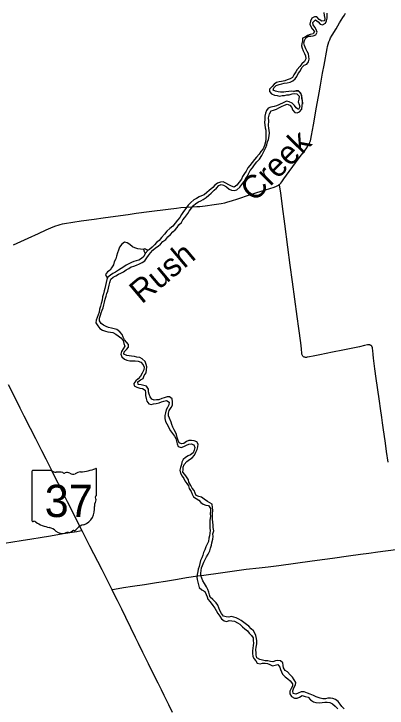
# Model space of a CAD drawing. Extents: x 0 to 680, y 0 to 440.
# Drawn here: x 136.6 to 190.2, y 233.7 to 333.5 of the extents above; entities that cross this region are included whole.
import ezdxf

# ---------------------------------------------------------------- set-up
doc = ezdxf.new("R2010")
doc.units = 0
for name, color, linetype in [('GM_X_County_Road', 7, 'Continuous'), ('GM_X_Minor_Lake', 7, 'Continuous'), ('GM_X_Minor_River', 7, 'Continuous'), ('GM_X_Minor_River_Text', 7, 'Continuous'), ('GM_X_State_Location', 7, 'Continuous'), ('GM_X_State_Route', 7, 'Continuous'), ('GM_X_State_Shield', 7, 'Continuous'), ('GM_X_Township_Road', 7, 'Continuous')]:
    doc.layers.add(name, color=color, linetype=linetype)

msp = doc.modelspace()

# ---------------------------------------------------------------- linework, layer by layer
at = {"layer": 'GM_X_County_Road'}
for points in [[(174.704, 308.957), (174.764, 309.006), (174.846, 309.082), (174.921, 309.163), (175.061, 309.334), (175.381, 309.78), (176.147, 310.846), (177.574, 312.783), (178.552, 314.1), (178.804, 314.46), (178.919, 314.649), (179.021, 314.845), (179.107, 315.049), (179.177, 315.258), (179.231, 315.472), (179.341, 316.009), (179.613, 317.517), (180.069, 320.101), (180.428, 322.147), (180.626, 323.222), (180.929, 324.946), (181.134, 326.131), (181.556, 328.499), (181.624, 328.818), (181.71, 329.132), (181.815, 329.441), (181.939, 329.742), (182.078, 330.038), (182.285, 330.421), (182.855, 331.353), (183.359, 332.2), (183.807, 332.95), (184.046, 333.314), (184.219, 333.577)], [(136.557, 300.312), (138.649, 301.261), (140.143, 301.938), (141.24, 302.432), (142.24, 302.872), (142.644, 303.036), (142.953, 303.143), (143.266, 303.235), (143.583, 303.31), (143.905, 303.37), (146.284, 303.724), (148.124, 303.989), (149.422, 304.184), (150.505, 304.337), (152.998, 304.667), (154.189, 304.837), (156.034, 305.068), (158.745, 305.425), (159.938, 305.58), (160.589, 305.65), (161.352, 305.702), (162.881, 305.783), (163.318, 305.819), (164.079, 305.916), (165.379, 306.098), (166.352, 306.25), (166.891, 306.353), (167.318, 306.455), (167.844, 306.608), (168.78, 306.914), (170.443, 307.461), (172.106, 308.004), (173.984, 308.598), (174.295, 308.713), (174.493, 308.812), (174.588, 308.871), (174.678, 308.935), (174.704, 308.957)], [(150.678, 250.749), (151.039, 250.812), (152.333, 251.037), (153.631, 251.239), (155.36, 251.511), (157.09, 251.783), (158.387, 251.987), (160.115, 252.266), (161.412, 252.474), (163.035, 252.722), (163.902, 252.845), (166.285, 253.187), (167.261, 253.318), (169.973, 253.682), (171.822, 253.893), (173.126, 254.04), (174.645, 254.241), (179.416, 254.892), (181.26, 255.135), (182.344, 255.281), (184.621, 255.598), (186.356, 255.83), (187.548, 256), (188.85, 256.173), (191.452, 256.527)]]:
    msp.add_lwpolyline(points, dxfattribs=at)
at = {"layer": 'GM_X_Minor_Lake'}
for points in [[(155.876, 299.531), (155.663, 299.562), (155.491, 299.671), (155.332, 299.714), (155.264, 299.635), (155.235, 299.515), (155.34, 299.38), (155.402, 299.138), (155.468, 299.07)], [(155.468, 299.07), (155.876, 299.531)]]:
    msp.add_lwpolyline(points, dxfattribs=at)
at = {"layer": 'GM_X_Minor_River'}
for points in [[(181.104, 333.695), (181.137, 333.253), (181.237, 332.837), (181.177, 332.464), (180.803, 332.417), (180.433, 332.677), (180.092, 333.043), (179.746, 333.076), (179.382, 332.854), (179.175, 332.444), (179.101, 332.004), (179.242, 331.667), (179.45, 331.316), (179.738, 330.964), (179.558, 330.606), (179.13, 330.519), (178.754, 330.392), (178.416, 330.143), (178.053, 329.989), (178.021, 329.615), (177.961, 329.242), (177.915, 328.882), (177.976, 328.547), (178.157, 328.156), (178.325, 327.792), (178.479, 327.442), (178.499, 327.014), (178.319, 326.629), (177.926, 326.302), (177.653, 325.932), (177.259, 325.497), (177.08, 325.153), (176.819, 324.703), (176.613, 324.358), (176.249, 324.151), (175.846, 323.983), (175.484, 323.856), (175.041, 323.756), (174.68, 323.695), (174.318, 323.621), (173.968, 323.399), (173.682, 323.057), (173.302, 322.675), (173.309, 322.314), (173.611, 321.975), (174.008, 321.808), (174.394, 321.735), (174.754, 321.662), (175.115, 321.736), (175.462, 321.744), (175.798, 321.832), (176.132, 321.867)], [(176.754, 322.351), (176.407, 322.384), (176.072, 322.309), (175.671, 322.275), (175.337, 322.241), (174.897, 322.248), (174.537, 322.267), (174.178, 322.367), (173.833, 322.506), (173.906, 322.866), (174.271, 323.194), (174.674, 323.334), (175.063, 323.435), (175.398, 323.51), (175.852, 323.556), (176.255, 323.683), (176.645, 323.863), (176.997, 324.138), (177.203, 324.496), (177.423, 324.893), (177.682, 325.25), (177.931, 325.794), (178.297, 326.135), (178.673, 326.236), (178.919, 326.593), (179.006, 326.993), (178.959, 327.381), (178.885, 327.756), (178.703, 328.094), (178.536, 328.457), (178.343, 328.915), (178.229, 329.304), (178.315, 329.651), (178.534, 330.021), (178.872, 330.283), (179.219, 330.277), (179.554, 330.312), (179.93, 330.493), (180.15, 330.837), (179.996, 331.227), (179.828, 331.564), (179.58, 331.902), (179.518, 332.237), (179.899, 332.632), (180.268, 332.359), (180.556, 331.993), (180.928, 331.893), (181.319, 332.128), (181.471, 332.486), (181.558, 332.886), (181.569, 333.594)], [(150.548, 295.369), (150.887, 295.671), (151.25, 295.852), (151.628, 296.06), (151.977, 296.228), (152.328, 296.422), (152.746, 296.683), (153.11, 296.904), (153.474, 297.152), (153.836, 297.24), (154.239, 297.393), (154.629, 297.547), (155.02, 297.781), (155.424, 298.015), (155.698, 298.425), (155.931, 298.782), (156.23, 299.138), (156.544, 299.547), (156.949, 299.861), (157.314, 300.096), (157.653, 300.411), (158.019, 300.752), (158.424, 301.08), (158.724, 301.422), (159.104, 301.79), (159.416, 302.146), (159.769, 302.461), (160.041, 302.804), (160.301, 303.187), (160.68, 303.502), (160.873, 303.886), (161.159, 304.229), (161.582, 304.797), (161.762, 305.155), (162.089, 305.577), (162.376, 305.96), (162.754, 306.234), (163.091, 306.456), (163.427, 306.598), (163.778, 306.819), (164.197, 307.106), (164.589, 307.42), (164.927, 307.709), (165.349, 308.156), (165.714, 308.445), (166.04, 308.8), (166.376, 308.942), (166.722, 308.869), (167.118, 308.622), (167.5, 308.281), (167.872, 308.168), (168.257, 308.082), (168.62, 308.21), (169.053, 308.563), (169.339, 308.946), (169.667, 309.409), (169.901, 309.819), (170.16, 310.162), (170.286, 310.508), (170.534, 310.958), (170.861, 311.381), (171.148, 311.804), (171.502, 312.199), (171.869, 312.607), (172.185, 313.136), (172.378, 313.521), (172.764, 314.263), (172.918, 314.688), (173.031, 315.074), (173.17, 315.446), (173.272, 315.952), (173.293, 316.393), (173.258, 316.741), (173.197, 317.076), (173.176, 317.438), (173.214, 318.132), (173.181, 318.533), (173.284, 319.12), (173.557, 319.53), (173.893, 319.631), (174.296, 319.798), (174.646, 319.98), (175.023, 320.161), (175.467, 320.367), (175.843, 320.495), (176.241, 320.368), (176.502, 320.029), (176.59, 319.694), (176.931, 319.301), (177.264, 319.282), (177.627, 319.423), (177.927, 319.792), (178.015, 320.299), (178.034, 320.633), (178.026, 320.967), (177.965, 321.342), (177.945, 321.717), (177.804, 322.067), (177.476, 322.406), (177.129, 322.438), (176.754, 322.351)], [(176.754, 322.351), (177.102, 322.412), (177.449, 322.393), (177.803, 322), (177.877, 321.651), (177.938, 321.302), (177.973, 320.968), (178.047, 320.632), (178.058, 320.485)], [(176.132, 321.867), (176.561, 322.007), (176.909, 322.028), (177.242, 322.009), (177.544, 321.67), (177.51, 321.229), (177.436, 320.829), (177.564, 320.44), (177.665, 320.104), (177.472, 319.72), (177.129, 319.966), (176.908, 320.33), (176.553, 320.67), (176.128, 320.838), (175.743, 320.924), (175.38, 320.756), (174.653, 320.394), (174.303, 320.253), (173.968, 320.151), (173.513, 320.078), (173.11, 319.938), (172.878, 319.594), (172.711, 319.223), (172.611, 318.783), (172.616, 318.275), (172.584, 317.942), (172.69, 317.098), (172.765, 316.763), (172.797, 316.308), (172.777, 315.894), (172.758, 315.546), (172.71, 315.079), (172.595, 314.587), (172.374, 314.109), (172.047, 313.7), (171.814, 313.343), (171.42, 312.909), (171.147, 312.552), (170.82, 312.116), (170.479, 311.708), (170.193, 311.338), (169.945, 310.901), (169.726, 310.544), (169.412, 310.135), (169.286, 309.736), (168.945, 309.314), (168.604, 308.865), (168.238, 308.563), (167.867, 308.703), (167.484, 308.937), (167.06, 309.171), (166.663, 309.351), (166.275, 309.304), (165.832, 309.151), (165.481, 308.889), (165.181, 308.533), (164.667, 308.114), (164.288, 307.8), (163.936, 307.498), (163.546, 307.344), (163.21, 307.176), (162.806, 306.955), (162.429, 306.761), (162.009, 306.367), (161.615, 305.972), (161.274, 305.497), (160.973, 305.074), (160.672, 304.638), (160.438, 304.228), (160.085, 303.819), (159.771, 303.41), (159.43, 303.001), (159.024, 302.634), (158.577, 302.24), (158.223, 301.818), (157.815, 301.344), (157.447, 300.909), (157.109, 300.62), (156.796, 300.278), (156.457, 299.963), (156.064, 299.622), (155.876, 299.531)], [(155.257, 299.606), (154.771, 299.683), (154.385, 299.743), (153.999, 299.843), (153.654, 299.996), (153.246, 300.323), (152.876, 300.57), (152.478, 300.67), (152.126, 300.395), (151.798, 299.946), (151.631, 299.534), (151.505, 299.136), (151.35, 298.644), (151.237, 298.285), (151.017, 297.874), (150.916, 297.408), (150.642, 296.985), (150.436, 296.641), (150.045, 296.42), (149.772, 296.05), (149.98, 295.593)], [(155.468, 299.07), (155.26, 298.619), (154.922, 298.318), (154.571, 298.096), (154.182, 297.996), (153.847, 297.908), (153.498, 297.78), (153.121, 297.559), (152.757, 297.351), (152.379, 297.117), (152.028, 296.882), (151.624, 296.648), (151.205, 296.374), (150.829, 296.193), (150.465, 295.959), (150.099, 295.657), (149.946, 295.299), (149.873, 294.873), (149.772, 294.447), (149.672, 294.034), (149.559, 293.688), (149.459, 293.236), (149.331, 292.81), (149.27, 292.343), (149.169, 291.877), (149.042, 291.465), (148.929, 291.039), (148.855, 290.626), (148.589, 289.869), (148.435, 289.47), (148.39, 289.11), (148.649, 288.652), (148.936, 288.259), (149.36, 288.039), (149.758, 287.912), (150.103, 287.813), (150.476, 287.753), (150.836, 287.694), (151.246, 287.46), (151.589, 287.227), (151.971, 286.913), (152.285, 286.547), (152.412, 286.131), (152.526, 285.755), (152.319, 285.357), (152.086, 284.987), (151.959, 284.588), (152.127, 284.211), (152.508, 283.844), (152.852, 283.705), (153.265, 283.604), (153.638, 283.612), (154.039, 283.645), (154.452, 283.598), (154.837, 283.431), (155.151, 283.065), (155.306, 282.715), (155.246, 282.329), (155.051, 281.864), (154.79, 281.428), (154.437, 281.059), (154.098, 280.731), (153.825, 280.361), (153.886, 280.026), (154.257, 279.86), (154.709, 279.719), (155.095, 279.632), (155.438, 279.412), (155.499, 279.037), (155.505, 278.623), (155.605, 278.194), (155.692, 277.831), (155.966, 277.453), (156.325, 277.353), (156.661, 277.468), (157.048, 277.488), (157.477, 277.575), (157.813, 277.716), (158.162, 277.831), (158.537, 277.918), (158.921, 277.711), (158.874, 277.311), (158.654, 276.941), (158.462, 276.596), (158.374, 276.157), (158.301, 275.757), (158.294, 275.33), (158.381, 274.927), (158.589, 274.59), (158.744, 274.253), (158.925, 273.903), (159.093, 273.566), (159.38, 273.2), (159.654, 272.822), (159.849, 272.471), (159.976, 272.095), (160.063, 271.719), (160.203, 271.303), (160.629, 271.189), (161.018, 271.303), (161.381, 271.51)], [(160.85, 267.63), (160.896, 268.004), (160.915, 268.338), (161.042, 268.71), (161.463, 269.17), (161.841, 269.445), (162.219, 269.679), (162.559, 270.061), (162.739, 270.486), (162.906, 270.884), (163.033, 271.269), (163.066, 271.643), (162.871, 271.994), (162.486, 272.12), (162.087, 272.18), (161.74, 272.186), (161.377, 272.045), (161.025, 271.77), (160.677, 271.709), (160.332, 271.822), (160.178, 272.185), (160.065, 272.614), (159.951, 273.031), (159.797, 273.367), (159.629, 273.704), (159.449, 274.108), (159.295, 274.498), (159.194, 274.834), (158.949, 275.372), (158.795, 275.736), (158.814, 276.096), (158.9, 276.469), (159.174, 276.905), (159.394, 277.263), (159.389, 277.757), (159.328, 278.146), (158.96, 278.472), (158.599, 278.452), (158.169, 278.298), (157.834, 278.197), (157.444, 278.03), (157.097, 278.022), (156.763, 277.974), (156.418, 278.127), (156.183, 278.465), (156.016, 278.855), (155.928, 279.191), (155.921, 279.552), (155.634, 279.971), (155.262, 280.07), (154.863, 280.184), (154.464, 280.23), (154.416, 280.592), (154.768, 280.88), (155.186, 281.1), (155.312, 281.513), (155.586, 281.882), (155.673, 282.322), (155.72, 282.749), (155.619, 283.098), (155.452, 283.515), (155.045, 283.896), (154.701, 284.102), (154.288, 284.135), (153.929, 284.235), (153.516, 284.282), (153.156, 284.341), (152.811, 284.414), (152.399, 284.567), (152.432, 284.928), (152.771, 285.27), (153.071, 285.612), (153.063, 285.973), (152.802, 286.311), (152.514, 286.664), (152.307, 287.041), (152.139, 287.418), (151.825, 287.798), (151.417, 288.112), (151.005, 288.225), (150.619, 288.325), (150.22, 288.412), (149.849, 288.565), (149.492, 288.758), (149.135, 289.005), (148.901, 289.396), (148.908, 289.77), (149.048, 290.169), (149.147, 290.514), (149.273, 290.9), (149.439, 291.245), (149.539, 291.657), (149.613, 292.044), (149.727, 292.483), (149.88, 292.908), (149.94, 293.308), (150.093, 293.653), (150.193, 294.092), (150.307, 294.491), (150.407, 294.89), (150.548, 295.369)], [(161.381, 271.51), (161.731, 271.665), (162.078, 271.686), (162.437, 271.546), (162.577, 271.183), (162.477, 270.784), (162.364, 270.412), (161.972, 270.097), (161.609, 269.956), (161.246, 269.749), (160.907, 269.434), (160.714, 269.076), (160.668, 268.716), (160.514, 268.304), (160.428, 267.931), (160.541, 267.502), (160.747, 267.044), (160.995, 266.706), (161.163, 266.369), (161.464, 266.003), (161.659, 265.653), (161.786, 265.29), (162.059, 264.844), (162.213, 264.454), (162.42, 264.077), (162.79, 263.857), (163.186, 263.596), (163.461, 263.258), (163.805, 263.052), (164.149, 262.899), (164.535, 262.839), (164.835, 262.407), (164.816, 262.059), (164.77, 261.659), (164.844, 261.284), (164.754, 260.684), (164.761, 260.323), (164.755, 259.976), (164.762, 259.602), (164.783, 259.24), (164.737, 258.854), (164.69, 258.48), (164.618, 258.134), (164.557, 257.667), (164.364, 257.283), (164.171, 256.912), (164.016, 256.46), (163.85, 256.102), (163.737, 255.69), (163.584, 255.332), (163.417, 254.933), (163.317, 254.521), (163.203, 254.068), (163.077, 253.71), (163.03, 253.336), (162.904, 252.937), (162.884, 252.564), (162.918, 252.189), (163.005, 251.813), (163.106, 251.464), (163.233, 251.061), (163.601, 250.708), (164.011, 250.474), (164.191, 250.07), (164.346, 249.72), (164.473, 249.384), (164.787, 248.978), (165.166, 248.477), (165.454, 248.112), (165.661, 247.747), (165.881, 247.329), (166.155, 246.924), (166.429, 246.545), (166.811, 246.258), (167.184, 246.185), (167.519, 246.3), (167.88, 246.281), (168.292, 246.221), (168.689, 245.974), (169.033, 245.781), (169.427, 245.427), (169.783, 245.127), (170.125, 244.827), (170.4, 244.489), (170.741, 244.162), (170.976, 243.825), (170.969, 243.424), (171.003, 243.062), (170.971, 242.702), (170.925, 242.342), (170.852, 241.969), (170.886, 241.581), (170.933, 241.193), (171.06, 240.843), (171.322, 240.505), (171.556, 240.167), (171.942, 240.08), (172.277, 240.168), (172.664, 240.175), (173.011, 240.143), (173.355, 239.99)], [(177.063, 235.733), (176.718, 235.846), (176.657, 236.221), (176.811, 236.646), (177.032, 237.07), (177.064, 237.417), (176.857, 237.808), (176.623, 238.186), (176.255, 238.526), (175.887, 238.92), (175.531, 239.139), (175.297, 239.531), (175.276, 239.865), (175.228, 240.213), (174.872, 240.5), (174.487, 240.586), (174.152, 240.525), (173.789, 240.397), (173.443, 240.416), (173.084, 240.529), (172.67, 240.523), (172.311, 240.609), (171.913, 240.722), (171.503, 240.97), (171.402, 241.332), (171.368, 241.68), (171.361, 242.081), (171.408, 242.494), (171.495, 242.947), (171.476, 243.389), (171.455, 243.736), (171.355, 244.166), (171.214, 244.502), (171.006, 244.84), (170.65, 245.126), (170.323, 245.492), (169.98, 245.752), (169.597, 246.012), (169.242, 246.312), (168.898, 246.531), (168.541, 246.711), (168.195, 246.81), (167.809, 246.883), (167.461, 246.809), (167.075, 246.842), (166.716, 246.955), (166.415, 247.334), (166.182, 247.765), (166.055, 248.142), (165.874, 248.519), (165.64, 248.87), (165.193, 249.332), (164.812, 249.645), (164.684, 249.995), (164.584, 250.398), (164.456, 250.774), (164.249, 251.165), (163.963, 251.61), (163.742, 252.002), (163.589, 252.418), (163.462, 252.795), (163.454, 253.129), (163.487, 253.502), (163.547, 253.876), (163.672, 254.221), (163.88, 254.685), (164.074, 255.083), (164.24, 255.441), (164.5, 255.864), (164.735, 256.328), (164.822, 256.728), (165.002, 257.125), (165.048, 257.486), (165.15, 258.018), (165.196, 258.365), (165.149, 258.767), (165.303, 259.218), (165.204, 259.674), (165.196, 260.022), (165.15, 260.437), (165.144, 260.878), (165.111, 261.306), (165.144, 261.667), (165.177, 262.107), (165.105, 262.576), (165.086, 263.017), (164.742, 263.237), (164.398, 263.429), (163.949, 263.731), (163.568, 264.058), (163.155, 264.118), (162.757, 264.272), (162.629, 264.608), (162.475, 264.984), (162.214, 265.336), (162.007, 265.727), (161.734, 266.199), (161.673, 266.548), (161.373, 266.954), (161.138, 267.292), (160.85, 267.63)], [(173.355, 239.99), (173.739, 239.783), (174.115, 239.884), (174.504, 239.998), (174.765, 239.633), (174.879, 239.284), (175.034, 238.947), (175.188, 238.584), (175.543, 238.244), (175.938, 237.917), (176.28, 237.644), (176.607, 237.237), (176.601, 236.877), (176.409, 236.532), (176.242, 236.161), (176.236, 235.8), (176.456, 235.383), (176.88, 235.175), (177.267, 235.169), (177.603, 235.323), (178.007, 235.531), (178.406, 235.404), (178.831, 235.277), (179.186, 234.937), (179.608, 234.649), (179.953, 234.536), (180.473, 234.474), (180.874, 234.521), (181.249, 234.582), (181.596, 234.576), (181.969, 234.53), (182.326, 234.324), (182.721, 233.983), (183.102, 233.629)], [(184.009, 233.615), (183.695, 233.954), (183.433, 234.292), (183.159, 234.657), (182.777, 234.958), (182.406, 235.111), (182.059, 235.157), (181.685, 235.136), (181.35, 235.061), (180.95, 235.081), (180.551, 235.141), (179.98, 235.324), (179.609, 235.531), (179.158, 235.712), (178.761, 235.892), (178.27, 236.061), (177.856, 236.054), (177.399, 235.888), (177.063, 235.733)]]:
    msp.add_lwpolyline(points, dxfattribs=at)
at = {"layer": 'GM_X_State_Route'}
msp.add_lwpolyline([(135.807, 280.204), (136.75, 278.351), (137.481, 276.882), (138.072, 275.71), (138.966, 273.956), (139.7, 272.488), (140.589, 270.731), (141.183, 269.561), (142.07, 267.803), (142.565, 266.827), (143.353, 265.265), (143.898, 264.192), (144.287, 263.409), (145.021, 261.941), (146.199, 259.594), (146.379, 259.238), (147.483, 257.056), (148.632, 254.818), (149.219, 253.644), (149.717, 252.67), (150.678, 250.749), (150.891, 250.322), (151.425, 249.245), (152.054, 247.969), (152.628, 246.788), (153.357, 245.318), (154.032, 243.944), (154.468, 243.061), (155.093, 241.784), (155.573, 240.801), (155.911, 240.114), (156.677, 238.541), (157.259, 237.364), (157.738, 236.381), (158.124, 235.595), (158.802, 234.223), (159.337, 233.145)], dxfattribs=at)
at = {"layer": 'GM_X_State_Shield'}
for p, q in [((139.21, 267.728), (139.21, 260.684)), ((142.02, 267.849), (139.301, 267.849)), ((148.491, 264.339), (148.491, 268.024)), ((148.49, 264.34), (148.491, 264.339))]:
    msp.add_line(p, q, dxfattribs=at)
for centre, radius, start, end in [((139.316, 267.743), 0.108, 98.1301, 188.1301), ((142.667, 268.667), 1.043, 231.61951, 271.11188), ((143.013, 263.894), 3.744, 80.48669, 94.98827), ((143.863, 267.779), 0.301, 219.79206, 297.10237), ((144.304, 266.965), 0.626, 54.46668, 119.14113), ((145.112, 268.082), 0.753, 233.85621, 294.82819), ((146.441, 265.698), 1.98, 97.34618, 120.76885), ((145.185, 277.453), 9.842, 275.84447, 288.90645), ((148.388, 268.039), 0.103, 351.86209, 97.738), ((148.467, 264.068), 0.16, 107.94398, 210.33697), ((147.45, 263.602), 0.96, 340.03296, 23.64957), ((148.381, 264.325), 0.111, 289.60381, 7.73413), ((145.736, 262.328), 2.462, 292.30889, 8.98584), ((148.861, 262.797), 0.698, 136.8065, 186.92959), ((139.317, 260.668), 0.108, 171.95839, 258.30661), ((139.334, 261.389), 0.828, 267.33899, 280.60386), ((139.503, 260.277), 0.298, 29.74838, 93.27175), ((143.272, 266.606), 7.108, 240.41292, 257.1985), ((141.153, 257.519), 2.224, 47.18416, 75.83597), ((145.066, 260.001), 0.795, 282.87319, 323.27711), ((146.775, 258.706), 1.348, 94.40312, 142.57675), ((143.558, 260.242), 1.411, 230.70037, 286.29184), ((144.373, 257.807), 1.16, 85.69512, 111.20995), ((144.476, 259.715), 0.752, 268.77702, 315.54927), ((145.157, 259.033), 0.212, 65.75173, 132.64842)]:
    msp.add_arc(centre, radius, start, end, dxfattribs=at)
at = {"layer": 'GM_X_Township_Road'}
for points in [[(190.321, 269.081), (190.107, 270.596), (189.947, 271.787), (189.638, 274.061), (189.538, 274.709), (189.42, 275.465), (189.237, 276.763), (189.076, 277.844), (188.809, 279.794), (188.629, 281.093), (188.434, 282.5), (188.247, 284.019), (188.18, 284.561), (188.128, 285.105), (188.093, 285.379), (188.081, 285.47), (188.065, 285.537), (188.048, 285.586), (188.024, 285.638), (188.002, 285.679), (187.966, 285.73), (187.935, 285.77), (187.892, 285.811), (187.858, 285.839), (187.803, 285.873), (187.759, 285.895), (187.702, 285.912), (187.646, 285.923), (187.594, 285.927), (187.545, 285.927), (187.484, 285.924), (187.376, 285.908), (186.95, 285.809), (186.203, 285.647), (185.239, 285.449), (183.845, 285.175), (182.342, 284.886), (180.523, 284.511), (179.558, 284.319), (179.025, 284.2), (178.703, 284.133), (178.595, 284.121), (178.482, 284.117), (178.37, 284.135), (178.273, 284.164), (178.177, 284.215), (178.094, 284.285), (178.03, 284.373), (177.984, 284.472), (177.955, 284.577), (177.938, 284.685), (177.889, 285.34), (177.79, 286.208), (177.531, 288.269), (177.296, 290.002), (176.617, 294.983), (176.289, 297.365), (175.93, 299.963), (175.495, 303.323), (175.177, 305.817), (174.922, 307.768), (174.844, 308.308), (174.775, 308.629), (174.704, 308.957)], [(125.519, 255.793), (125.588, 255.798), (126.992, 256.019), (127.963, 256.179), (129.366, 256.411), (131.415, 256.755), (133.464, 257.102), (135.297, 257.411), (137.672, 257.8), (139.183, 258.045), (140.37, 258.242), (141.88, 258.499), (143.714, 258.799), (145.658, 259.114), (146.089, 259.188), (146.379, 259.238)]]:
    msp.add_lwpolyline(points, dxfattribs=at)

# ---------------------------------------------------------------- texts
at = {"layer": 'GM_X_Minor_River_Text'}
for s, height, rotation, p in [('Creek', 3.3341, 45.03185, (171.132, 306.333)), ('Rush', 3.3339, 40.02177, (154.967, 291.706))]:
    msp.add_text(s, height=height, rotation=rotation, dxfattribs=at).set_placement(p)
at = {"layer": 'GM_X_State_Location'}
for s in ['s', 'r']:
    msp.add_text(s, height=0.00667, dxfattribs=at).set_placement((143.746, 263.738))
msp.add_text('37', height=0.00667, rotation=0.00001, dxfattribs=at).set_placement((142.067, 263.253))
at = {"layer": 'GM_X_State_Shield'}
msp.add_text('37', height=4.6406, dxfattribs=at).set_placement((141.039, 261.18))

doc.saveas('drawing.dxf')
